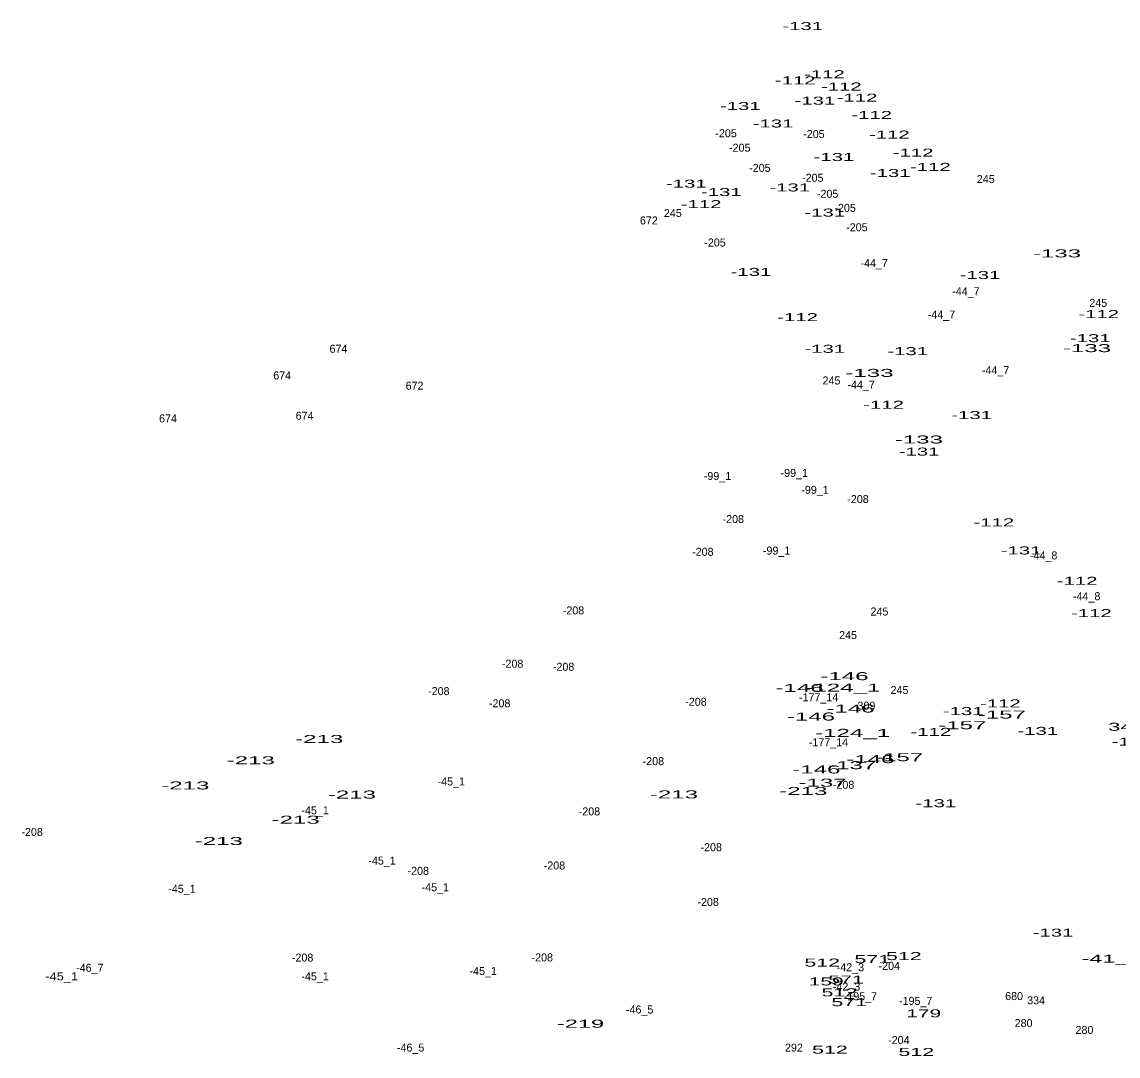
# Model space of a CAD drawing. Extents: x -658595 to -655205, y -1004347 to -1000147.
# Drawn here: x -657427 to -656879, y -1000664 to -1000147 of the extents above; entities that cross this region are included whole.
import ezdxf
from ezdxf.enums import TextEntityAlignment as Align

# ---------------------------------------------------------------- set-up
doc = ezdxf.new("R2010")
doc.units = 0
doc.header["$LTSCALE"] = 1.6
doc.layers.add('24', color=7, linetype='Continuous')

msp = doc.modelspace()

# ---------------------------------------------------------------- texts
at = {"layer": '24'}
for s, width, p in [('-131', 1.9, (-657037.037, -1000150.75)), ('-112', 1.9, (-657040.767, -1000177.9)), ('-112', 1.9, (-657026.177, -1000174.83)), ('-112', 1.9, (-657017.727, -1000180.98)), ('-131', 1.9, (-657030.947, -1000188.04)), ('-112', 1.9, (-657009.847, -1000186.55)), ('-131', 1.9, (-657068.217, -1000190.7)), ('-112', 1.9, (-657002.557, -1000195.2)), ('-131', 1.9, (-657051.867, -1000199.45)), ('-112', 1.9, (-656993.717, -1000204.99)), ('-131', 1.9, (-657021.437, -1000216.19)), ('-112', 1.9, (-656981.817, -1000214.02)), ('-112', 1.9, (-656973.177, -1000221.13)), ('-131', 1.9, (-656993.287, -1000224.18)), ('-131', 1.9, (-657095.227, -1000229.51)), ('-131', 1.9, (-657077.727, -1000233.7)), ('-131', 1.9, (-657043.497, -1000231.41)), ('-112', 1.9, (-657087.797, -1000239.76)), ('-131', 1.9, (-657025.997, -1000243.97)), ('-133', 2.25, (-656909.901, -1000264.37)), ('-131', 1.9, (-657062.897, -1000273.62)), ('-131', 1.9, (-656948.407, -1000275.17)), ('-112', 1.9, (-657039.597, -1000296.23)), ('-112', 1.9, (-656889.067, -1000294.69)), ('-131', 1.9, (-656893.257, -1000306.73)), ('-131', 1.9, (-657025.997, -1000312.05)), ('-131', 1.9, (-656984.537, -1000313.22)), ('-133', 2.25, (-656894.891, -1000311.71)), ('-133', 2.25, (-657003.661, -1000324.1)), ('-112', 1.9, (-656996.587, -1000340.03)), ('-131', 1.9, (-656952.587, -1000345.16)), ('-133', 2.25, (-656978.941, -1000357.38)), ('-131', 1.9, (-656978.837, -1000363.42)), ('-112', 1.9, (-656941.487, -1000398.8)), ('-131', 1.9, (-656927.867, -1000412.83)), ('-112', 1.9, (-656899.817, -1000428)), ('-112', 1.9, (-656892.717, -1000444.14)), ('-146', 2.25, (-657016.151, -1000475.66)), ('-146', 2.25, (-657038.601, -1000481.56)), ('-124_1', 2.25, (-657016.963, -1000481.4)), ('-146', 2.25, (-657013.111, -1000491.83)), ('-112', 1.9, (-656938.217, -1000489.27)), ('-146', 2.25, (-657032.891, -1000495.83)), ('-131', 1.9, (-656956.777, -1000493.11)), ('-157', 2.25, (-656937.465, -1000494.86)), ('-157', 2.25, (-656957.245, -1000500.18)), ('341', 2.05, (-656875.183, -1000500.96)), ('-213', 2.25, (-657278.741, -1000507.06)), ('-124_1', 2.25, (-657012.053, -1000504)), ('-112', 1.9, (-656972.967, -1000503.49)), ('-131', 1.9, (-656919.497, -1000503)), ('-131', 1.9, (-656872.337, -1000508.33)), ('-213', 2.25, (-657312.971, -1000517.71)), ('-146', 2.25, (-657003.221, -1000517.14)), ('-157', 2.25, (-656988.815, -1000516.16)), ('-146', 2.25, (-657030.231, -1000522.27)), ('-137', 2.25, (-657012.285, -1000520.15)), ('-137', 2.25, (-657027.115, -1000528.9)), ('-213', 2.25, (-657345.681, -1000530.27)), ('-213', 2.25, (-657262.381, -1000534.83)), ('-213', 2.25, (-657101.391, -1000534.74)), ('-213', 2.25, (-657036.731, -1000533.03)), ('-131', 1.9, (-656970.467, -1000539.15)), ('-213', 2.25, (-657290.531, -1000547.39)), ('-213', 2.25, (-657328.951, -1000558.04)), ('-131', 1.9, (-656911.887, -1000603.83)), ('571', 2, (-657002.243, -1000617.08)), ('512', 2, (-656986.457, -1000615.55)), ('-41_1', 2.2, (-656882.613, -1000616.86)), ('512', 2, (-657027.257, -1000618.81)), ('-45_1', 1.2, (-657407.49, -1000625.68)), ('159', 1.95, (-657025.273, -1000628.22)), ('571', 2, (-657015.363, -1000627.26)), ('512', 2, (-657018.707, -1000633.7)), ('571', 2, (-657013.753, -1000638.58)), ('179', 1.95, (-656976.517, -1000644.17)), ('-219', 2.2, (-657148.105, -1000649.35)), ('512', 2, (-657023.417, -1000662.32)), ('512', 2, (-656980.217, -1000663.47))]:
    msp.add_text(s, height=4, dxfattribs=dict(at, width=width)).set_placement(p, align=Align.CENTER)
for s, p in [('-205', (-657075.349, -1000204.32)), ('-205', (-657031.419, -1000204.7)), ('-205', (-657068.499, -1000211.55)), ('-205', (-657058.429, -1000221.64)), ('-205', (-657031.989, -1000226.58)), ('245', (-656945.501, -1000227.18)), ('-205', (-657024.569, -1000234.57)), ('245', (-657101.961, -1000244.19)), ('-205', (-657015.819, -1000241.61)), ('672', (-657113.938, -1000247.91)), ('-205', (-657009.929, -1000251.32)), ('-205', (-657080.869, -1000258.93)), ('-44_7', (-657001.326, -1000269.21)), ('-44_7', (-656955.436, -1000283.3)), ('245', (-656889.281, -1000289.09)), ('-44_7', (-656967.626, -1000294.92)), ('674', (-657269.123, -1000312.03)), ('674', (-657297.273, -1000325.35)), ('-44_7', (-656940.586, -1000322.72)), ('672', (-657231.088, -1000330.48)), ('245', (-657022.641, -1000327.89)), ('-44_7', (-657007.796, -1000329.97)), ('674', (-657354.333, -1000346.85)), ('674', (-657286.053, -1000345.52)), ('-99_1', (-657079.637, -1000375.62)), ('-99_1', (-657041.237, -1000374.08)), ('-99_1', (-657030.867, -1000382.53)), ('-208', (-657009.389, -1000387.16)), ('-208', (-657071.739, -1000397.15)), ('-208', (-657086.959, -1000413.51)), ('-99_1', (-657050.067, -1000412.89)), ('-44_8', (-656916.571, -1000415.31)), ('-44_8', (-656895.061, -1000435.69)), ('-208', (-657151.619, -1000442.81)), ('245', (-656998.671, -1000443.35)), ('245', (-657014.361, -1000455.12)), ('-208', (-657182.049, -1000469.44)), ('-208', (-657156.569, -1000470.97)), ('-208', (-657218.949, -1000483.14)), ('-177_14', (-657029.075, -1000486.2)), ('245', (-656988.651, -1000482.59)), ('-208', (-657188.519, -1000489.23)), ('-208', (-657090.389, -1000488.46)), ('309', (-657005.157, -1000490.4)), ('-177_14', (-657024.125, -1000508.65)), ('-208', (-657111.689, -1000518.13)), ('-45_1', (-657212.72, -1000528.27)), ('-208', (-657016.589, -1000529.93)), ('-45_1', (-657280.8, -1000542.73)), ('-208', (-657143.649, -1000543.25)), ('-208', (-657422.249, -1000553.53)), ('-208', (-657082.779, -1000561.13)), ('-45_1', (-657247.33, -1000567.84)), ('-208', (-657229.229, -1000572.93)), ('-208', (-657161.139, -1000570.27)), ('-45_1', (-657347.36, -1000581.92)), ('-45_1', (-657220.7, -1000581.16)), ('-208', (-657084.309, -1000588.53)), ('-208', (-657287.029, -1000616.31)), ('-208', (-657167.219, -1000616.23)), ('-46_7', (-657393.398, -1000621.38)), ('-45_1', (-657196.74, -1000623.01)), ('-42_3', (-657013.177, -1000621.15)), ('-204', (-656993.743, -1000620.43)), ('-45_1', (-657280.8, -1000625.68)), ('-42_3', (-657015.087, -1000630.77)), ('-195_7', (-657008.207, -1000635.65)), ('-195_7', (-656980.537, -1000637.94)), ('680', (-656931.357, -1000635.54)), ('334', (-656920.361, -1000637.66)), ('-46_5', (-657118.542, -1000642.25)), ('280', (-656926.601, -1000649.05)), ('280', (-656896.171, -1000652.47)), ('-46_5', (-657233.032, -1000661.28)), ('292', (-657041.413, -1000661.3)), ('-204', (-656988.983, -1000657.53))]:
    msp.add_text(s, height=4, dxfattribs=at).set_placement(p, align=Align.CENTER)

doc.saveas('drawing.dxf')
